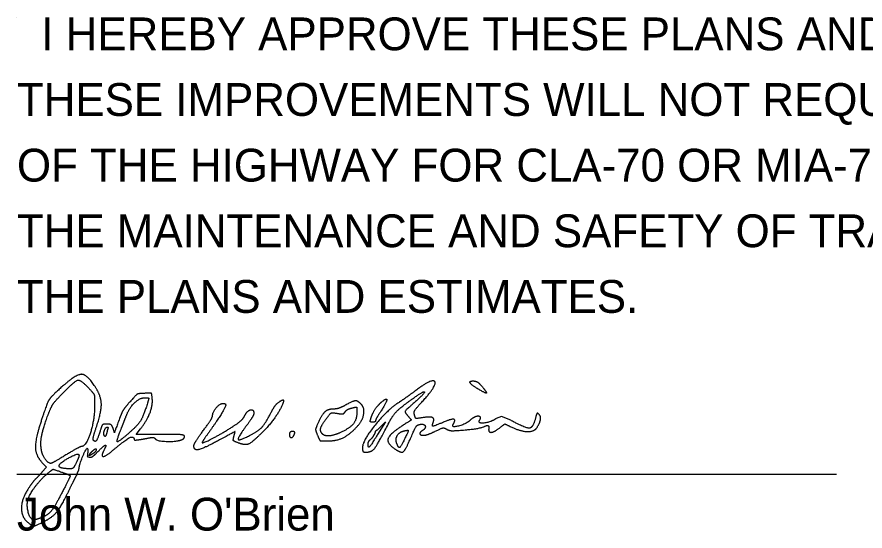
# Model space of a CAD drawing. Extents: x 0 to 34, y 0 to 22.
# Drawn here: x 24.528 to 28.149, y 8.684 to 10.877 of the extents above; entities that cross this region are included whole.
import ezdxf

# ---------------------------------------------------------------- set-up
doc = ezdxf.new("R2010")
doc.units = 0
doc.layers.add('SH_Data', color=7, linetype='Continuous')
doc.layers.add('SH_Text', color=7, linetype='Continuous')

msp = doc.modelspace()

# ---------------------------------------------------------------- linework, layer by layer
at = {"layer": 'SH_Data'}
for p, q in [((24.5279, 10.875), (24.5279, 10.875)), ((24.5279, 8.9262), (28.0279, 8.9262))]:
    msp.add_line(p, q, dxfattribs=at)
at = {"layer": 'SH_Text'}
msp.add_line((26.4932, 9.2925), (26.4932, 9.2925), dxfattribs=at)
for points in [[(26.636, 9.1565), (26.597, 9.1731), (26.574, 9.1646)], [(26.0685, 9.1173), (26.1019, 9.1505), (26.0672, 9.0956)], [(25.1404, 9.0966), (25.0375, 9.0966), (25.0558, 9.1206)], [(24.6346, 8.9772), (24.654, 8.9566), (24.6346, 8.9348)]]:
    msp.add_lwpolyline(points, dxfattribs=at)
for points in [[(24.8676, 9.2902), (24.8304, 9.3511), (24.781, 9.3542), (24.7199, 9.2995)], [(24.7219, 9.2706), (24.7758, 9.3259), (24.8, 9.3304), (24.836, 9.2918)], [(26.2529, 9.2302), (26.3225, 9.305), (26.3023, 9.3379), (26.2232, 9.2785)], [(26.4932, 9.2925), (26.467, 9.3085), (26.4588, 9.3248), (26.4772, 9.3244)], [(26.4772, 9.3244), (26.4887, 9.3241), (26.5064, 9.3108), (26.5222, 9.2906)], [(24.7199, 9.2995), (24.6737, 9.2582), (24.656, 9.2292), (24.6319, 9.1557)], [(24.6595, 9.1766), (24.672, 9.2107), (24.69, 9.2379), (24.7219, 9.2706)], [(24.836, 9.2918), (24.8564, 9.2699), (24.8592, 9.261), (24.8592, 9.2177)], [(24.8663, 9.1257), (24.888, 9.1897), (24.8885, 9.2559), (24.8676, 9.2902)], [(25.0723, 9.2716), (25.0465, 9.2708), (25.0363, 9.2649), (25.0106, 9.2359)], [(25.1056, 9.2482), (25.1034, 9.271), (25.1012, 9.2725), (25.0723, 9.2716)], [(26.2232, 9.2785), (26.2012, 9.262), (26.1724, 9.2416), (26.1592, 9.2331)], [(26.2332, 9.2597), (26.2688, 9.2843), (26.2661, 9.2682), (26.2292, 9.2362)], [(26.5222, 9.2906), (26.5367, 9.2722), (26.5254, 9.2729), (26.4932, 9.2925)], [(25.0106, 9.2359), (24.9936, 9.2167), (24.976, 9.1911), (24.9715, 9.1788)], [(24.9955, 9.1777), (25.008, 9.2099), (25.052, 9.2526), (25.0726, 9.2526)], [(25.0869, 9.2346), (25.0699, 9.1788), (25.0454, 9.1369), (25.013, 9.1083)], [(25.0558, 9.1206), (25.0834, 9.1568), (25.1083, 9.2207), (25.1056, 9.2482)], [(25.0726, 9.2526), (25.0893, 9.2526), (25.0915, 9.2499), (25.0869, 9.2346)], [(25.64, 9.2292), (25.6828, 9.2648), (25.629, 9.1584), (25.5787, 9.1082)], [(25.9977, 9.225), (25.982, 9.2407), (25.9646, 9.2396), (25.9291, 9.2206)], [(26.0397, 9.1666), (26.0462, 9.1874), (26.0692, 9.2216), (26.0861, 9.2357)], [(26.0861, 9.2357), (26.1081, 9.2539), (26.1061, 9.232), (26.0827, 9.1971)], [(26.1167, 9.1474), (26.1337, 9.18), (26.1732, 9.218), (26.2332, 9.2597)], [(26.2292, 9.2362), (26.1879, 9.2003), (26.1832, 9.1903), (26.1992, 9.1727)], [(24.8592, 9.2177), (24.8592, 9.1578), (24.8225, 9.0446), (24.803, 9.0446)], [(25.4192, 9.2214), (25.4192, 9.2136), (25.3786, 9.1487), (25.3398, 9.0946)], [(25.3632, 9.1766), (25.3632, 9.1916), (25.3949, 9.2286), (25.4078, 9.2286)], [(25.4078, 9.2286), (25.4141, 9.2286), (25.4192, 9.2254), (25.4192, 9.2214)], [(25.5007, 9.1766), (25.5102, 9.1974), (25.5392, 9.2045), (25.5392, 9.1861)], [(25.611, 9.1861), (25.6205, 9.2045), (25.6335, 9.2239), (25.64, 9.2292)], [(25.883, 9.2046), (25.857, 9.2046), (25.8307, 9.1828), (25.8153, 9.1487)], [(25.9291, 9.2206), (25.9127, 9.2118), (25.892, 9.2046), (25.883, 9.2046)], [(25.9291, 9.1925), (25.9325, 9.1985), (25.9451, 9.2058), (25.9572, 9.2088)], [(25.9572, 9.2088), (25.9776, 9.2139), (25.9792, 9.2125), (25.9792, 9.1901)], [(25.9786, 9.128), (26.0029, 9.1537), (26.0137, 9.209), (25.9977, 9.225)], [(26.1592, 9.2331), (26.1093, 9.2011), (26.0032, 9.0692), (26.0032, 9.0392)], [(26.2252, 9.1794), (26.2222, 9.1911), (26.2302, 9.2057), (26.2529, 9.2302)], [(24.6328, 9.0272), (24.6272, 9.0565), (24.6384, 9.1192), (24.6595, 9.1766)], [(24.9715, 9.1788), (24.9427, 9.1013), (24.9449, 9.105), (24.9381, 9.1235)], [(24.9722, 9.1186), (24.9814, 9.1417), (24.9919, 9.1683), (24.9955, 9.1777)], [(25.3232, 9.1126), (25.3452, 9.1424), (25.3632, 9.1712), (25.3632, 9.1766)], [(25.4494, 9.1297), (25.4726, 9.1445), (25.4957, 9.1656), (25.5007, 9.1766)], [(25.5392, 9.1861), (25.5392, 9.1802), (25.5248, 9.1562), (25.5072, 9.1325)], [(25.5203, 9.0912), (25.5584, 9.1108), (25.5884, 9.1422), (25.611, 9.1861)], [(25.8326, 9.0979), (25.8214, 9.1091), (25.828, 9.1361), (25.8483, 9.1627)], [(25.8483, 9.1627), (25.8668, 9.187), (25.8727, 9.1898), (25.8962, 9.186)], [(25.8962, 9.186), (25.9142, 9.1831), (25.925, 9.1852), (25.9291, 9.1925)], [(25.9792, 9.1901), (25.9792, 9.1606), (25.9497, 9.1234), (25.9121, 9.1056)], [(26.0467, 9.1486), (26.0374, 9.1486), (26.0356, 9.1532), (26.0397, 9.1666)], [(26.0827, 9.1971), (26.0698, 9.1779), (26.0592, 9.1591), (26.0592, 9.1554)], [(26.1992, 9.1727), (26.2118, 9.1587), (26.2113, 9.1571), (26.1899, 9.1438)], [(26.2584, 9.1675), (26.2339, 9.1636), (26.2289, 9.1654), (26.2252, 9.1794)], [(26.3044, 9.1449), (26.3116, 9.1636), (26.2926, 9.1729), (26.2584, 9.1675)], [(26.5033, 9.1567), (26.5134, 9.1731), (26.4821, 9.1744), (26.4648, 9.1583)], [(26.574, 9.1646), (26.5525, 9.1482), (26.4941, 9.1419), (26.5033, 9.1567)], [(26.7424, 9.1678), (26.7319, 9.1249), (26.7008, 9.1216), (26.636, 9.1565)], [(26.7567, 9.1824), (26.7506, 9.1884), (26.7465, 9.1842), (26.7424, 9.1678)], [(26.7476, 9.1246), (26.7612, 9.1455), (26.7656, 9.1735), (26.7567, 9.1824)], [(24.6319, 9.1557), (24.6059, 9.0764), (24.607, 9.0067), (24.6346, 8.9772)], [(24.8545, 9.0707), (24.8517, 9.0735), (24.8571, 9.0982), (24.8663, 9.1257)], [(24.9121, 9.1406), (24.8965, 9.1406), (24.8905, 9.1345), (24.8829, 9.1106)], [(24.9062, 9.1246), (24.9197, 9.1312), (24.913, 9.1121), (24.9118, 9.1043)], [(24.9381, 9.1235), (24.934, 9.1346), (24.9249, 9.1406), (24.9121, 9.1406)], [(25.3196, 9.0606), (25.3278, 9.0606), (25.4081, 9.1033), (25.4494, 9.1297)], [(25.5072, 9.1325), (25.47, 9.0827), (25.4747, 9.0678), (25.5203, 9.0912)], [(25.8153, 9.1487), (25.8032, 9.1219), (25.8026, 9.1135), (25.8111, 9.0929)], [(25.8552, 9.0686), (25.8926, 9.0686), (25.9478, 9.0952), (25.9786, 9.128)], [(26.0178, 9.0206), (26.0424, 9.0206), (26.0675, 9.0528), (26.1167, 9.1474)], [(26.0592, 9.1554), (26.0592, 9.1517), (26.0536, 9.1486), (26.0467, 9.1486)], [(26.1899, 9.1438), (26.1224, 9.1019), (26.1042, 9.0589), (26.143, 9.0335)], [(26.208, 9.0787), (26.2265, 9.1221), (26.2371, 9.1373), (26.25, 9.1392)], [(26.25, 9.1392), (26.2679, 9.1418), (26.2747, 9.1222), (26.2592, 9.1126)], [(26.3611, 9.1531), (26.3092, 9.1319), (26.2989, 9.1304), (26.3044, 9.1449)], [(26.3905, 9.1395), (26.4015, 9.1572), (26.3872, 9.1638), (26.3611, 9.1531)], [(26.4648, 9.1583), (26.4453, 9.1401), (26.3809, 9.1238), (26.3905, 9.1395)], [(26.4563, 9.1171), (26.5084, 9.122), (26.5469, 9.1416), (26.5419, 9.1167)], [(26.59, 9.1251), (26.6104, 9.1411), (26.6116, 9.1412), (26.6411, 9.1271)], [(26.6411, 9.1271), (26.6784, 9.1093), (26.7368, 9.1079), (26.7476, 9.1246)], [(24.8829, 9.1106), (24.8723, 9.0773), (24.8621, 9.0631), (24.8545, 9.0707)], [(24.8992, 9.1001), (24.8992, 9.1043), (24.8998, 9.1099), (24.9062, 9.1246)], [(24.9118, 9.1043), (24.9078, 9.087), (24.8992, 9.0886), (24.8992, 9.1001)], [(25.013, 9.1083), (24.962, 9.0635), (24.9513, 9.0662), (24.9722, 9.1186)], [(25.2432, 9.0875), (25.2432, 9.0938), (25.2122, 9.0966), (25.1404, 9.0966)], [(25.2832, 9.0475), (25.2832, 9.0535), (25.3012, 9.0828), (25.3232, 9.1126)], [(25.3398, 9.0946), (25.3264, 9.0759), (25.3173, 9.0606), (25.3196, 9.0606)], [(25.4546, 9.0889), (25.4595, 9.1084), (25.4579, 9.108), (25.3928, 9.0728)], [(25.5787, 9.1082), (25.5329, 9.0624), (25.5023, 9.0488), (25.4719, 9.0604)], [(25.7039, 9.1086), (25.6969, 9.1086), (25.6912, 9.1029), (25.6912, 9.0959)], [(25.6912, 9.0959), (25.6912, 9.0818), (25.7085, 9.0843), (25.7134, 9.0991)], [(25.7134, 9.0991), (25.7151, 9.1043), (25.7109, 9.1086), (25.7039, 9.1086)], [(25.8111, 9.0929), (25.8201, 9.0712), (25.8248, 9.0686), (25.8552, 9.0686)], [(25.9121, 9.1056), (25.8843, 9.0924), (25.8422, 9.0883), (25.8326, 9.0979)], [(26.0672, 9.0956), (26.041, 9.0516), (26.0272, 9.0373), (26.0272, 9.0539)], [(26.0392, 9.0766), (26.0458, 9.0821), (26.0512, 9.0914), (26.0546, 9.0967)], [(26.0546, 9.0967), (26.0583, 9.1034), (26.059, 9.1122), (26.0685, 9.1173)], [(26.1499, 9.0571), (26.143, 9.0753), (26.1592, 9.1057), (26.1786, 9.1107)], [(26.1786, 9.1107), (26.1989, 9.1161), (26.1993, 9.1095), (26.1812, 9.0731)], [(26.2592, 9.1126), (26.2466, 9.1048), (26.2499, 9.0926), (26.2647, 9.0926)], [(26.2647, 9.0926), (26.2721, 9.0926), (26.2942, 9.1004), (26.3138, 9.1099)], [(26.3138, 9.1099), (26.3413, 9.1232), (26.3526, 9.1251), (26.3634, 9.1184)], [(26.3634, 9.1184), (26.3732, 9.1123), (26.401, 9.1119), (26.4563, 9.1171)], [(26.5419, 9.1167), (26.5423, 9.1034), (26.5677, 9.1075), (26.59, 9.1251)], [(24.9324, 9.0243), (24.9663, 9.0529), (25.0264, 9.0971), (25.0295, 9.0718)], [(25.0295, 9.0718), (25.0437, 9.0731), (25.0683, 9.0769), (25.0843, 9.0801)], [(25.0843, 9.0801), (25.1028, 9.0839), (25.1154, 9.0829), (25.1188, 9.0773)], [(25.1188, 9.0773), (25.1245, 9.0681), (25.209, 9.0652), (25.2306, 9.0735)], [(25.2306, 9.0735), (25.2375, 9.0761), (25.2432, 9.0824), (25.2432, 9.0875)], [(25.3928, 9.0728), (25.3258, 9.0365), (25.2832, 9.0267), (25.2832, 9.0475)], [(25.4719, 9.0604), (25.4533, 9.0674), (25.4504, 9.0722), (25.4546, 9.0889)], [(26.0272, 9.0539), (26.0272, 9.0609), (26.0326, 9.0711), (26.0392, 9.0766)], [(26.1812, 9.0731), (26.1659, 9.0423), (26.1573, 9.0379), (26.1499, 9.0571)], [(26.173, 9.0207), (26.1786, 9.0208), (26.1944, 9.0469), (26.208, 9.0787)], [(24.6725, 8.9726), (24.6619, 8.9726), (24.6366, 9.0074), (24.6328, 9.0272)], [(24.803, 9.0446), (24.7991, 9.0446), (24.7691, 9.0284), (24.7365, 9.0086)], [(24.792, 8.9444), (24.7951, 8.9734), (24.8361, 9.0628), (24.8283, 9.0021)], [(24.8283, 9.0021), (24.8419, 8.9972), (24.8569, 9.0056), (24.8708, 9.0202)], [(24.8603, 9.02), (24.8459, 9.0093), (24.833, 9.0039), (24.841, 9.0157)], [(24.841, 9.0157), (24.8436, 9.0195), (24.8482, 9.0235), (24.8544, 9.0286)], [(24.8544, 9.0286), (24.8647, 9.0389), (24.8678, 9.028), (24.8603, 9.02)], [(24.8708, 9.0202), (24.8973, 9.0478), (24.9119, 9.0524), (24.8995, 9.0291)], [(24.8995, 9.0291), (24.886, 9.0038), (24.9047, 9.0011), (24.9324, 9.0243)], [(26.0032, 9.0392), (26.0032, 9.0265), (26.0079, 9.0206), (26.0178, 9.0206)], [(26.143, 9.0335), (26.1538, 9.0264), (26.1673, 9.0207), (26.173, 9.0207)], [(24.7365, 9.0086), (24.7039, 8.9888), (24.6751, 8.9726), (24.6725, 8.9726)], [(24.709, 8.9658), (24.7125, 8.9763), (24.786, 9.0165), (24.7916, 9.0109)], [(24.7916, 9.0109), (24.794, 9.0085), (24.7897, 8.9935), (24.7821, 8.9776)], [(24.6594, 8.9304), (24.6806, 8.9477), (24.6826, 8.9479), (24.7183, 8.9357)], [(24.7518, 8.9495), (24.7233, 8.9511), (24.7062, 8.9576), (24.709, 8.9658)], [(24.7821, 8.9776), (24.7724, 8.9573), (24.7633, 8.9489), (24.7518, 8.9495)], [(24.7792, 8.9159), (24.7828, 8.921), (24.7859, 8.9315), (24.792, 8.9444)], [(24.5745, 8.8165), (24.5802, 8.8392), (24.631, 8.9073), (24.6594, 8.9304)], [(24.6346, 8.9348), (24.624, 8.9229), (24.6112, 8.9094), (24.6063, 8.9048)], [(24.7183, 8.9357), (24.7386, 8.9288), (24.7552, 8.9213), (24.7552, 8.9191)], [(24.7552, 8.9191), (24.7552, 8.9169), (24.7405, 8.8868), (24.7226, 8.8522)], [(24.7491, 8.8553), (24.7618, 8.8822), (24.7762, 8.909), (24.7792, 8.9159)], [(24.6063, 8.9048), (24.6013, 8.9003), (24.5878, 8.8823), (24.5763, 8.8648)], [(24.5763, 8.8648), (24.5453, 8.8179), (24.5487, 8.7373), (24.5824, 8.7147)], [(24.7226, 8.8522), (24.688, 8.7858), (24.6592, 8.7513), (24.6287, 8.7397)], [(24.6426, 8.7243), (24.6803, 8.7435), (24.7185, 8.7905), (24.7491, 8.8553)], [(24.599, 8.7326), (24.5855, 8.7326), (24.5682, 8.7916), (24.5745, 8.8165)], [(24.6287, 8.7397), (24.6185, 8.7358), (24.6052, 8.7326), (24.599, 8.7326)], [(24.5824, 8.7147), (24.5964, 8.7054), (24.6097, 8.7075), (24.6426, 8.7243)]]:
    msp.add_open_spline(points, degree=2, dxfattribs=at)

# ---------------------------------------------------------------- texts
for s, p in [('  I HEREBY APPROVE THESE PLANS AND DECLARE THAT THE MAKING OF ', (24.5279, 10.735)), ('THESE IMPROVEMENTS WILL NOT REQUIRE THE CLOSING TO TRAFFIC', (24.5279, 10.455)), ('OF THE HIGHWAY FOR CLA-70 OR MIA-75, AND THAT PROVISIONS FOR', (24.5279, 10.175)), ('THE MAINTENANCE AND SAFETY OF TRAFFIC WILL BE AS SET FORTH ON', (24.5279, 9.895)), ('THE PLANS AND ESTIMATES.', (24.5279, 9.615)), ("John W. O'Brien", (24.5279, 8.6862))]:
    msp.add_text(s, height=0.14, dxfattribs=at).set_placement(p)

doc.saveas('drawing.dxf')
